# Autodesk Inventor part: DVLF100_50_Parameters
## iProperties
Created: 2010-03
Part Number: DVLF100_50_Parameters
Document SubType Name: Modeling
Designer: TB
Density: 1 g/cm^3
Slaglengde: 100.000 mm
Vinkel_Plussport: 0.00 deg
Vinkel_Minusport: 0.00 deg
Forlengelse_rør: 0.000 mm
Author: TB
